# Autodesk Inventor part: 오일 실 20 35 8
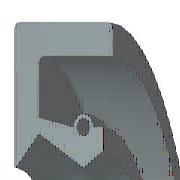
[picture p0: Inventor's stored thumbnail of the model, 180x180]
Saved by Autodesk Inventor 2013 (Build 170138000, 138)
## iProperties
IsCustomPart: 0
Created: 2018-09
Part Number: 오일 실 20 35 8
Material: 고무
Description: 오일-실
Document SubType Name: Modeling
Standard: KS B 2804
Standards Organization: KS
Language: ko-KR
Size Designation: D - 20 35 8
Categories: <MemberInstance><Categories><Category DisplayName="샤프트 부품" InternalName="7f7aeb1f-a693-4053-b835-cee3144e0d98" Mnemonic="SHFT"><Category DisplayName="실링" Intern
Density: 0.93 g/cm^3
Mass: 2.54606 g
Surface Area: 35.9421 cm^2
Volume: 2.7377 cm^3
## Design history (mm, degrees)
revolve "본체" stored, may be unused: angle "d17" = 90 deg
revolve "스프링1" stored, may be unused: angle "d18" = 90 deg
body "Solid1"
sketch "스케치1"
  geometry: L1 (0, 17.5)-(8, 17.5); L2 (8, 15.75)-(1.75, 15.75); L3 (1.75, 11.75)-(4.9, 10); L4 (4.9, 10)-(0, 10); L5 (0, 0)-(9.586, 0) reference; L6 (4.9, 10)-(6.3, 10.875); L7 (0, 18)-(0, -3) reference; L8 (-1.941, 0)-(11.507, 0) reference; L9 (4.2, 12.1)-(1.75, 12.71); L10 (1.75, 12.71)-(1.75, 15.75); L11 (0, 17.5)-(0, 10.088); L12 (4.9, 10)-(0, 10); L13 (1.75, 11.75)-(0.152, 10.028); L14 (8, 17.5)-(8, 15.75); L15 (5.6, 12.1)-(6.3, 12.1); L16 (6.3, 12.1)-(6.3, 10.875); C1 r 0.455 at (4.9, 12.1); A1 r 0.7 centre (4.9, 12.1) between (5.6, 12.1) and (4.2, 12.1); A2 r 0.088 centre (0.088, 10.088) between (0, 10.088) and (0.152, 10.028); 1 further point
  constraints: 28 end point, 5 horizontal alignment, 5 point on line, 4 point on circle, 4 vertical alignment, 3 centre point, 3 tangent, 2 collinear, 2 horizontal, 2 perpendicular, 1 coincident, 1 parallel
  dimensions: "d0" = 35 diameter of L1 L5 (= SD2); "d1" = 1.75 distance of L1.end L2.start (= SD); "d2" = 0.91 diameter of C1 (= SPDI); "d3" = 1.4 diameter of A1 (= SPDA); "d4" = 20 diameter of L3.end L5 (= NND); "d5" = 23.5 diameter of L3.start L5 (= TKDM); "d7" = 25.42 diameter of L9.end L5 (= TKDM + 0.24 x SWDT); "d8" = 1.75 distance between parallel lines of L11 L10 (= SD); "d9" = 4.9 distance from line of L11 C1.centre (= SPDST); "d10" = 24.2 diameter of C1.centre L5 (= HLDM); "d11" = 0.0875 radius of A2 (= 0.25 x LAB); "d12" = 6.3 distance between parallel lines of L11 L16 (= SDI); "d13" = 21.75 diameter of L6.end L5 (= ABDM); "d14" = 8 distance from line of L11 L1.end (= SWDT)
fillet "모깎기1" dims "d6" = 0.3 (= RR)
other parameters: "SD2" = 35 [user parameter; used in 1 equation term], "SWDT" = 8 [user parameter; used in 2 equation terms], "RR" = 0.3 [user parameter; used in 1 equation term], "SD" = 1.75 [user parameter; used in 2 equation terms], "NND" = 20 [user parameter; used in 1 equation term], "SPDA" = 1.4 [user parameter; used in 1 equation term], "SPDI" = 0.91 [user parameter; used in 1 equation term], "TKDM" = 23.5 [user parameter; used in 2 equation terms], "HLDM" = 24.2 [user parameter; used in 1 equation term], "ABDM" = 21.75 [user parameter; used in 1 equation term], "SDI" = 6.3 [user parameter; used in 1 equation term], "SPDST" = 4.9 [user parameter; used in 1 equation term], "LAB" = 0.35 [user parameter; used in 1 equation term], "d15" = 0, "d16" = 0, "d19" = 0
